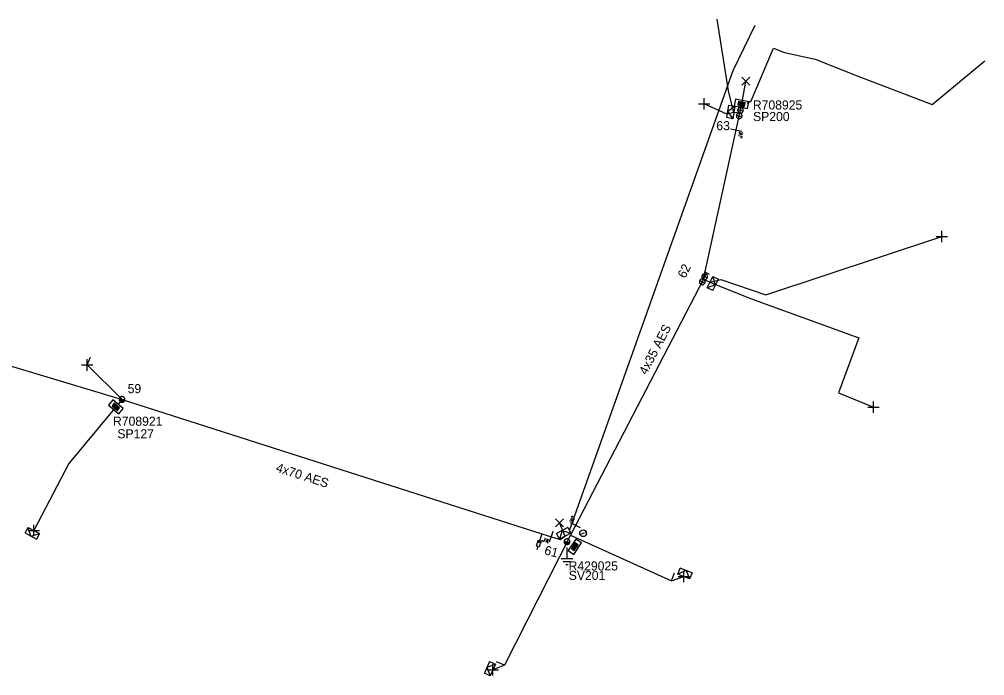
# Model space of a CAD drawing. Extents: x -540247 to -537390, y -1183887 to -1180355.
# Drawn here: x -537607.2 to -537501.2, y -1180536.7 to -1180464.6 of the extents above; entities that cross this region are included whole.
import ezdxf

# ---------------------------------------------------------------- set-up
doc = ezdxf.new("R2010")
doc.units = 0
for name, color, linetype in [('Vrstva 1', 7, 'Continuous'), ('Vrstva 10', 7, 'Continuous'), ('Vrstva 13', 7, 'Continuous'), ('Vrstva 14', 7, 'Continuous'), ('Vrstva 15', 7, 'Continuous'), ('Vrstva 16', 7, 'Continuous'), ('Vrstva 18', 7, 'Continuous'), ('Vrstva 2', 7, 'Continuous'), ('Vrstva 28', 7, 'Continuous'), ('Vrstva 29', 7, 'Continuous'), ('Vrstva 30', 7, 'Continuous'), ('Vrstva 31', 7, 'Continuous'), ('Vrstva 34', 7, 'Continuous'), ('Vrstva 36', 7, 'Continuous'), ('Vrstva 5', 7, 'Continuous'), ('Vrstva 50', 7, 'Continuous'), ('Vrstva 51', 7, 'Continuous'), ('Vrstva 52', 7, 'Continuous'), ('Vrstva 54', 7, 'Continuous'), ('Vrstva 59', 7, 'Continuous'), ('Vrstva 8', 7, 'Continuous'), ('Vrstva 9', 7, 'Continuous')]:
    doc.layers.add(name, color=color, linetype=linetype)

# ---------------------------------------------------------------- blocks, each defined once
blk = doc.blocks.new('NN440')
at = {"layer": 'Vrstva 2'}
for points in [[(0.63, 0), (0.63, 0.06), (0.62, 0.13), (0.6, 0.19), (0.58, 0.25), (0.55, 0.31), (0.51, 0.37), (0.47, 0.42), (0.42, 0.46), (0.37, 0.51), (0.32, 0.54), (0.26, 0.57), (0.2, 0.59), (0.13, 0.61), (0.07, 0.62), (0, 0.63), (-0.06, 0.62), (-0.13, 0.61), (-0.19, 0.59), (-0.26, 0.57), (-0.31, 0.54), (-0.37, 0.51), (-0.42, 0.46), (-0.47, 0.42), (-0.51, 0.37), (-0.54, 0.31), (-0.57, 0.25), (-0.6, 0.19), (-0.62, 0.13), (-0.63, 0.06), (-0.63, 0), (-0.63, -0.07), (-0.62, -0.14), (-0.6, -0.2), (-0.57, -0.26), (-0.54, -0.32), (-0.51, -0.37), (-0.47, -0.43), (-0.42, -0.47), (-0.37, -0.51), (-0.31, -0.55), (-0.26, -0.58), (-0.19, -0.6), (-0.13, -0.62), (-0.06, -0.63), (0, -0.63), (0.07, -0.63), (0.13, -0.62), (0.2, -0.6), (0.26, -0.58), (0.32, -0.55), (0.37, -0.51), (0.42, -0.47), (0.47, -0.43), (0.51, -0.37), (0.55, -0.32), (0.58, -0.26), (0.6, -0.2), (0.62, -0.14), (0.63, -0.07), (0.63, 0)], [(-0.63, 0), (0.63, 0)], [(-0.6, -0.18), (0.57, -0.18)], [(-0.51, -0.32), (0.5, -0.32)], [(-0.37, -0.47), (0.35, -0.47)]]:
    blk.add_lwpolyline(points, dxfattribs=at)
blk = doc.blocks.new('NN840')
at = {"layer": 'Vrstva 15'}
for points in [[(0, 0.62), (0, -0.63)], [(-0.75, -0.71), (-0.75, -0.66)], [(-0.73, -0.76), (-0.75, -0.71)], [(-0.66, -0.8), (-0.73, -0.76)], [(-0.63, -0.8), (-0.66, -0.8)], [(-0.56, -0.76), (-0.63, -0.8)], [(-0.54, -0.71), (-0.56, -0.76)], [(-0.54, -0.38), (-0.54, -0.71)], [(-0.33, -0.38), (-0.33, -0.8)], [(-0.33, -0.64), (-0.13, -0.38)], [(-0.26, -0.56), (-0.09, -0.8)]]:
    blk.add_lwpolyline(points, dxfattribs=at)
blk = doc.blocks.new('NN770')
at = {"layer": 'Vrstva 10'}
for p, q in [((0, 0.19), (0, 0.26)), ((0, -0.28), (0, 0.11))]:
    blk.add_line(p, q, dxfattribs=at)
blk.add_circle((0, -0.01), 0.375, dxfattribs=at)
blk = doc.blocks.new('NN800')
at = {"layer": 'Vrstva 1'}
for points in [[(-0.44, 0.44), (0.44, -0.44)], [(-0.44, -0.44), (0.44, 0.44)]]:
    blk.add_lwpolyline(points, dxfattribs=at)
blk = doc.blocks.new('NN820')
at = {"layer": 'Vrstva 13'}
for points in [[(0, 0), (0, -1.05)], [(-0.16, -0.81), (0.16, -0.81)], [(-0.16, -1.47), (-0.16, -0.81)], [(0, -1.05), (-0.06, -0.93)], [(0, -1.05), (0.06, -0.93)], [(0.16, -0.81), (0.16, -1.47)], [(0.16, -1.47), (-0.16, -1.47)], [(0, -1.47), (0, -1.87)]]:
    blk.add_lwpolyline(points, dxfattribs=at)
blk = doc.blocks.new('NN620')
at = {"layer": 'Vrstva 8'}
for points in [[(0.75, 0), (-0.75, 0)], [(-0.75, 0), (-0.75, -0.75)], [(0.75, -0.75), (0.75, 0)], [(-0.75, -0.75), (0.75, -0.75)], [(0.37, -0.18), (-0.38, -0.18)], [(-0.38, -0.18), (-0.38, -0.56)], [(-0.38, -0.56), (0.37, -0.56)], [(0.32, -0.23), (-0.33, -0.23)], [(-0.33, -0.23), (-0.33, -0.51)], [(-0.33, -0.51), (0.32, -0.51)], [(0.27, -0.27), (-0.28, -0.27)], [(-0.28, -0.27), (-0.28, -0.46)], [(-0.28, -0.46), (0.27, -0.46)], [(0.23, -0.32), (-0.23, -0.32)], [(-0.23, -0.32), (-0.23, -0.42)], [(-0.23, -0.42), (0.23, -0.42)], [(-0.19, -0.37), (0.19, -0.37)], [(0.23, -0.42), (0.23, -0.32)], [(0.27, -0.46), (0.27, -0.27)], [(0.32, -0.51), (0.32, -0.23)], [(0.37, -0.56), (0.37, -0.18)]]:
    blk.add_lwpolyline(points, dxfattribs=at)
blk = doc.blocks.new('NN630')
at = {"layer": 'Vrstva 9'}
for points in [[(0, -0.7), (-0.7, 0)], [(-0.7, -0.7), (-0.7, 0), (0.7, 0), (0.7, -0.7)], [(-0.7, -0.7), (0.7, -0.7)], [(0, -0.7), (0.7, 0)]]:
    blk.add_lwpolyline(points, dxfattribs=at)
blk = doc.blocks.new('NN810')
at = {"layer": 'Vrstva 14'}
for points in [[(0, -0.64), (0, -1.89)], [(0.63, -1.89), (-0.62, -1.89)], [(0.39, -2.2), (-0.4, -2.2)], [(0, -2.52), (-0.12, -2.52)], [(0.14, -2.52), (0, -2.52)]]:
    blk.add_lwpolyline(points, dxfattribs=at)
blk = doc.blocks.new('NN430')
at = {"layer": 'Vrstva 2'}
for points in [[(0, 0), (0, 0.07), (-0.01, 0.13), (-0.03, 0.19), (-0.05, 0.25), (-0.08, 0.31), (-0.12, 0.37), (-0.16, 0.42), (-0.21, 0.46), (-0.26, 0.51), (-0.31, 0.54), (-0.37, 0.57), (-0.43, 0.59), (-0.5, 0.61), (-0.56, 0.62), (-0.63, 0.63), (-0.69, 0.62), (-0.75, 0.61), (-0.82, 0.59), (-0.88, 0.57), (-0.94, 0.54), (-0.99, 0.51), (-1.04, 0.46), (-1.09, 0.42), (-1.13, 0.37), (-1.17, 0.31), (-1.2, 0.25), (-1.22, 0.19), (-1.24, 0.13), (-1.25, 0.07), (-1.25, 0), (-1.25, -0.07), (-1.24, -0.13), (-1.22, -0.19), (-1.2, -0.25), (-1.17, -0.31), (-1.13, -0.37), (-1.09, -0.42), (-1.04, -0.46), (-0.99, -0.51), (-0.94, -0.54), (-0.88, -0.57), (-0.82, -0.59), (-0.75, -0.61), (-0.69, -0.62), (-0.62, -0.62), (-0.56, -0.62), (-0.5, -0.61), (-0.43, -0.59), (-0.37, -0.57), (-0.31, -0.54), (-0.26, -0.51), (-0.21, -0.46), (-0.16, -0.42), (-0.12, -0.37), (-0.08, -0.31), (-0.05, -0.25), (-0.03, -0.19), (-0.01, -0.13), (0, -0.07), (0, 0)], [(-1.25, 0), (1.25, 0)], [(-0.62, 0.62), (-0.62, -0.62)], [(1.25, 0), (1.25, 0.07), (1.24, 0.13), (1.22, 0.19), (1.2, 0.25), (1.17, 0.31), (1.13, 0.37), (1.09, 0.42), (1.04, 0.46), (0.99, 0.51), (0.94, 0.54), (0.88, 0.57), (0.82, 0.59), (0.75, 0.61), (0.69, 0.62), (0.62, 0.63), (0.56, 0.62), (0.5, 0.61), (0.43, 0.59), (0.37, 0.57), (0.31, 0.54), (0.26, 0.51), (0.21, 0.46), (0.16, 0.42), (0.12, 0.37), (0.08, 0.31), (0.05, 0.25), (0.03, 0.19), (0.01, 0.13), (0, 0.07), (0, 0), (0, -0.07), (0.01, -0.13), (0.03, -0.19), (0.05, -0.25), (0.08, -0.31), (0.12, -0.37), (0.16, -0.42), (0.21, -0.46), (0.26, -0.51), (0.31, -0.54), (0.37, -0.57), (0.43, -0.59), (0.5, -0.61), (0.56, -0.62), (0.63, -0.62), (0.69, -0.62), (0.75, -0.61), (0.82, -0.59), (0.88, -0.57), (0.94, -0.54), (0.99, -0.51), (1.04, -0.46), (1.09, -0.42), (1.13, -0.37), (1.17, -0.31), (1.2, -0.25), (1.22, -0.19), (1.24, -0.13), (1.25, -0.07), (1.25, 0)], [(0.62, 0.62), (0.62, -0.62)], [(1.57, 0.62), (1.57, -0.62)]]:
    blk.add_lwpolyline(points, dxfattribs=at)
blk = doc.blocks.new('NN510')
at = {"layer": 'Vrstva 2'}
blk.add_lwpolyline([(0, 0), (0, 0.94)], dxfattribs=at)

msp = doc.modelspace()

# ---------------------------------------------------------------- linework, layer by layer
at = {"layer": 'Vrstva 5'}
msp.add_lwpolyline([(-537595.92, -1180506.36), (-537596.36, -1180506.89)], dxfattribs=at)
at = {"layer": 'Vrstva 50'}
for points in [[(-537532.06, -1180493.17), (-537528.07, -1180474.93)], [(-537532.06, -1180493.17), (-537546.67, -1180521.26)], [(-537614.79, -1180500.69), (-537595.92, -1180506.36)], [(-537595.92, -1180506.36), (-537549.81, -1180521.1), (-537547.8, -1180521.74)]]:
    msp.add_lwpolyline(points, dxfattribs=at)
at = {"layer": 'Vrstva 52'}
for points in [[(-537546.79, -1180520.76), (-537528.8, -1180470.26), (-537526.4, -1180465.29)], [(-537528.73, -1180474.86), (-537529.32, -1180472.5), (-537530.57, -1180464.64)], [(-537527.27, -1180473.86), (-537526.81, -1180473.57), (-537524.38, -1180467.81), (-537523.17, -1180468.28), (-537519.79, -1180469), (-537515.18, -1180470.86), (-537506.94, -1180473.98), (-537501.18, -1180469.18)], [(-537528.73, -1180474.86), (-537529.5, -1180475.04), (-537531.97, -1180473.92)], [(-537528.07, -1180474.93), (-537528.73, -1180474.86)], [(-537528.07, -1180474.93), (-537527.96, -1180474.29)], [(-537531.36, -1180493.48), (-537530.14, -1180493.2), (-537525.21, -1180494.89), (-537505.9, -1180488.46)], [(-537532.06, -1180493.17), (-537531.36, -1180493.48)], [(-537531.36, -1180493.48), (-537526.9, -1180495.28), (-537515, -1180499.6), (-537517.25, -1180505.62), (-537513.39, -1180507.21)], [(-537596.74, -1180507.34), (-537601.76, -1180513.39), (-537605.6, -1180520.74)]]:
    msp.add_lwpolyline(points, dxfattribs=at)
at = {"layer": 'Vrstva 54'}
for points in [[(-537595.92, -1180506.36), (-537599.76, -1180502.58)], [(-537547.8, -1180521.74), (-537547.25, -1180521.37)]]:
    msp.add_lwpolyline(points, dxfattribs=at)
at = {"layer": 'Vrstva 59'}
for points in [[(-537527.83, -1180473.72), (-537527.41, -1180471.43)], [(-537547.25, -1180521.37), (-537547.89, -1180519.9)]]:
    msp.add_lwpolyline(points, dxfattribs=at)
at = {"layer": 'Vrstva 8'}
for points in [[(-537546.67, -1180521.26), (-537553.92, -1180535.53), (-537555.2, -1180536.04)], [(-537546.67, -1180521.26), (-537535.58, -1180526.28), (-537534.23, -1180525.79)]]:
    msp.add_lwpolyline(points, dxfattribs=at)

# ---------------------------------------------------------------- block references
at = {"layer": 'Vrstva 13', "xscale": 0.5}
for name, p, yscale, rotation in [('NN430', (-537528.07, -1180474.93), 0.5000000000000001, 77.06613890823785), ('NN430', (-537532.06, -1180493.17), 0.5, 64.58831668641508), ('NN440', (-537547.05, -1180521.98), 0.5, -14.840994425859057)]:
    msp.add_blockref(name, p, dxfattribs=dict(at, yscale=yscale, rotation=rotation))
at = {"layer": 'Vrstva 13'}
for p, rotation in [((-537599.76, -1180502.58), -24.31930835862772), ((-537535.58, -1180526.28), -21.579905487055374), ((-537553.92, -1180535.53), 65.56743886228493)]:
    msp.add_blockref('NN510', p, dxfattribs=dict(at, rotation=rotation))
at = {"layer": 'Vrstva 13', "xscale": 0.5, "yscale": 0.5}
msp.add_blockref('NN440', (-537595.92, -1180506.36), dxfattribs=at)
at = {"layer": 'Vrstva 15', "rotation": -0.11001624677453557}
msp.add_blockref('NN810', (-537547.05, -1180521.98), dxfattribs=at)
at = {"layer": 'Vrstva 16', "rotation": -17.73503338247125}
msp.add_blockref('NN820', (-537549.81, -1180521.1), dxfattribs=at)
at = {"layer": 'Vrstva 18'}
for p, rotation in [((-537528.48, -1180476.79), 77.66091386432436), ((-537546.12, -1180520.18), -117.48856111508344), ((-537548.8, -1180521.42), -19.42392766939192)]:
    msp.add_blockref('NN840', p, dxfattribs=dict(at, rotation=rotation))
at = {"layer": 'Vrstva 28'}
for p, rotation in [((-537527.96, -1180474.29), 169.20759167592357), ((-537596.36, -1180506.89), -39.72528888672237), ((-537546.51, -1180522.32), 56.20470620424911)]:
    msp.add_blockref('NN620', p, dxfattribs=dict(at, rotation=rotation))
at = {"layer": 'Vrstva 31'}
for p, rotation in [((-537528.73, -1180474.86), -99.60520275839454), ((-537531.36, -1180493.48), 63.622313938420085), ((-537605.6, -1180520.74), -28.87322780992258), ((-537547.25, -1180521.37), -153.1741199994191), ((-537534.23, -1180525.79), 158.42009448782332), ((-537555.2, -1180536.04), -114.43256113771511)]:
    msp.add_blockref('NN630', p, dxfattribs=dict(at, rotation=rotation))
at = {"layer": 'Vrstva 34'}
for p in [(-537527.41, -1180471.43), (-537547.89, -1180519.9)]:
    msp.add_blockref('NN800', p, dxfattribs=at)
for p, rotation in [((-537531.97, -1180473.92), 45), ((-537505.9, -1180488.46), 45), ((-537599.76, -1180502.58), 45), ((-537513.39, -1180507.21), 45), ((-537605.6, -1180520.74), 45.00000009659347), ((-537534.23, -1180525.79), 45), ((-537555.2, -1180536.04), 45)]:
    msp.add_blockref('NN800', p, dxfattribs=dict(at, rotation=rotation))
at = {"layer": 'Vrstva 36', "rotation": -69.34108890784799}
msp.add_blockref('NN770', (-537545.27, -1180521.04), dxfattribs=at)

# ---------------------------------------------------------------- texts
at = {"layer": 'Vrstva 14'}
for s, rotation, p in [('63', 0.052, (-537530.65, -1180476.82)), ('62', 64.18, (-537534.06, -1180493.14)), ('61', 345.159, (-537549.61, -1180523.34))]:
    msp.add_text(s, height=1, rotation=rotation, dxfattribs=at).set_placement(p)
msp.add_text('59', height=1, dxfattribs=at).set_placement((-537595.3, -1180505.67))
at = {"layer": 'Vrstva 29'}
for s, p in [('R708925', (-537526.64, -1180474.54)), ('R708921', (-537596.91, -1180509.25)), ('R429025', (-537546.88, -1180525.13))]:
    msp.add_text(s, height=1, dxfattribs=at).set_placement(p)
at = {"layer": 'Vrstva 30'}
for s, p in [('SP200', (-537526.62, -1180475.81)), ('SP127', (-537596.43, -1180510.63)), ('SV201', (-537546.86, -1180526.17))]:
    msp.add_text(s, height=1, dxfattribs=at).set_placement(p)
at = {"layer": 'Vrstva 51'}
for s, rotation, p in [('4x35 AES', 62.511, (-537538.32, -1180503.74)), ('4x70 AES', 342.275, (-537579.09, -1180514.26))]:
    msp.add_text(s, height=1, rotation=rotation, dxfattribs=at).set_placement(p)

doc.saveas('drawing.dxf')
